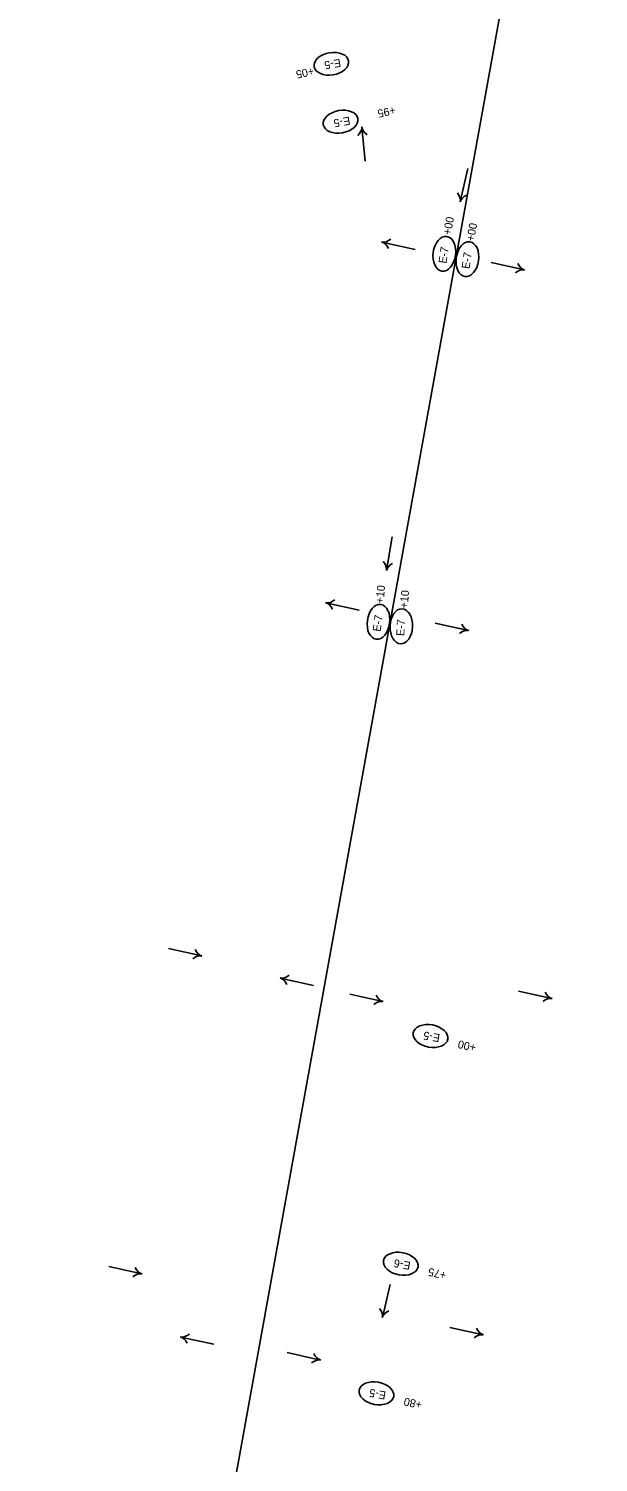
# Model space of a CAD drawing. Extents: x 669236 to 673912, y 735758 to 754788.
# Drawn here: x 670518 to 670963, y 741936 to 743056 of the extents above; entities that cross this region are included whole.
import ezdxf

# ---------------------------------------------------------------- set-up
doc = ezdxf.new("R2010")
doc.units = 0
for name, color, linetype in [('Default', 7, 'Continuous'), ('R_Erosion_2', 7, 'Continuous'), ('R_Erosion_3', 7, 'Continuous'), ('R_Flow Arrows', 7, 'Continuous')]:
    doc.layers.add(name, color=color, linetype=linetype)

msp = doc.modelspace()

# ---------------------------------------------------------------- linework, layer by layer
at = {"layer": 'Default'}
msp.add_line((670518, 741030.5), (670962.6, 743492), dxfattribs=at)
at = {"layer": 'R_Erosion_2'}
for centre, major_axis in [((670754.2, 743028.2), (-13.5, -2.2)), ((670761.4, 742983), (-13.5, -2.4)), ((670842.4, 742879.9), (1.9, 13.6)), ((670860.4, 742875.7), (1.9, 13.6)), ((670791, 742592.5), (1.8, 13.6)), ((670808.8, 742589), (0.6, 13.7))]:
    msp.add_ellipse(centre, major_axis=major_axis, ratio=0.638788, dxfattribs=at)
at = {"layer": 'R_Erosion_3'}
for centre in [(670831.6, 742269.1), (670808.4, 742091.3), (670789.4, 741990.1)]:
    msp.add_ellipse(centre, major_axis=(-13.5, 2.5), ratio=0.638788, dxfattribs=at)
at = {"layer": 'R_Flow Arrows'}
for p, q in [((670778, 742978.7), (670780.5, 742952.3)), ((670854.8, 742920.5), (670860.6, 742946.4)), ((670793.6, 742889), (670819.5, 742883.3)), ((670904.9, 742867.3), (670879, 742873.1)), ((670797.2, 742632.7), (670801.6, 742658.9)), ((670749.9, 742607.4), (670775.9, 742601.7)), ((670861.3, 742585.7), (670835.3, 742591.5)), ((670653, 742331.6), (670627.1, 742337.4)), ((670714.3, 742314.3), (670740.2, 742308.6)), ((670794.4, 742296), (670768.5, 742301.8)), ((670926.4, 742298.4), (670900.4, 742304.2)), ((670606.3, 742083.4), (670580.4, 742089.2)), ((670794, 742049.3), (670800.2, 742075.2)), ((670872.7, 742035.9), (670846.8, 742041.6)), ((670636.5, 742034.1), (670662.4, 742028.4)), ((670745.7, 742016.1), (670719.8, 742021.9))]:
    msp.add_line(p, q, dxfattribs=at)
for centre, major_axis, start_param, end_param in [((670757.9, 742977.3), (20.1, 1.9), 5.662936, 6.259934), ((670798, 742980.9), (-20.1, -1.9), 0.023252, 0.620249), ((670835.1, 742924.6), (19.7, -4.4), 0.023252, 0.620249), ((670874.4, 742915.7), (-19.7, 4.4), 5.662936, 6.259934), ((670788.8, 742869.5), (4.4, 19.7), 5.662936, 6.259934), ((670797.7, 742908.8), (-4.4, -19.7), 0.023252, 0.620249), ((670900.8, 742847.6), (4.4, 19.7), 0.023252, 0.620249), ((670909.7, 742886.9), (-4.4, -19.7), 5.662936, 6.259934), ((670777.3, 742635.8), (19.9, -3.3), 0.023252, 0.620249), ((670817, 742628.9), (-19.9, 3.3), 5.662936, 6.259934), ((670754.1, 742627.2), (-4.4, -19.7), 0.023252, 0.620249), ((670745.1, 742587.9), (4.4, 19.7), 5.662936, 6.259934), ((670866.1, 742605.3), (-4.4, -19.7), 5.662936, 6.259934), ((670857.1, 742566), (4.4, 19.7), 0.023252, 0.620249), ((670648.9, 742311.9), (4.4, 19.7), 0.023252, 0.620249), ((670657.8, 742351.2), (-4.4, -19.7), 5.662936, 6.259934), ((670709.5, 742294.8), (4.4, 19.7), 5.662936, 6.259934), ((670718.4, 742334.1), (-4.4, -19.7), 0.023252, 0.620249), ((670790.3, 742276.3), (4.4, 19.7), 0.023252, 0.620249), ((670799.2, 742315.6), (-4.4, -19.7), 5.662936, 6.259934), ((670922.3, 742278.7), (4.4, 19.7), 0.023252, 0.620249), ((670931.2, 742318), (-4.4, -19.7), 5.662936, 6.259934), ((670602.2, 742063.7), (4.4, 19.7), 0.023252, 0.620249), ((670611.1, 742103), (-4.4, -19.7), 5.662936, 6.259934), ((670774.3, 742053.8), (19.6, -4.8), 0.023252, 0.620249), ((670813.5, 742044.2), (-19.6, 4.8), 5.662936, 6.259934), ((670877.5, 742055.5), (-4.4, -19.7), 5.662936, 6.259934), ((670631.7, 742014.6), (4.4, 19.7), 5.662936, 6.259934), ((670640.6, 742053.9), (-4.4, -19.7), 0.023252, 0.620249), ((670868.6, 742016.1), (4.4, 19.7), 0.023252, 0.620249), ((670741.6, 741996.4), (4.4, 19.7), 0.023252, 0.620249), ((670750.6, 742035.7), (-4.4, -19.7), 5.662936, 6.259934)]:
    msp.add_ellipse(centre, major_axis=major_axis, ratio=0.5625, start_param=start_param, end_param=end_param, dxfattribs=at)

# ---------------------------------------------------------------- texts
at = {"layer": 'R_Erosion_2'}
for s, rotation, p in [('+05', 192.1215, (670739.9, 743025.7)), ('E-5', 189.2797, (670761.1, 743032.1)), ('+95', 192.4629, (670803.6, 742995.2)), ('E-5', 190.1319, (670768.3, 742987)), ('+00', 79.2728, (670847.4, 742894.2)), ('+00', 79.2728, (670865.5, 742889.3)), ('E-7', 81.9991, (670844, 742872)), ('E-7', 81.9991, (670862, 742867.8)), ('+10', 84.6001, (670794.9, 742606.7)), ('+10', 84.6001, (670813.7, 742602.8)), ('E-7', 82.5982, (670792.6, 742584.6)), ('E-7', 87.3558, (670811.1, 742581.3))]:
    msp.add_text(s, height=6.25, rotation=rotation, dxfattribs=at).set_placement(p)
at = {"layer": 'R_Erosion_3'}
for s, rotation, p in [('E-5', 169.6427, (670839.4, 742270.4)), ('+00', 167.5318, (670867.6, 742262.9)), ('E-6', 169.6427, (670816.4, 742092.6)), ('+75', 167.5318, (670844.4, 742085.1)), ('E-5', 169.6427, (670797.2, 741991.4)), ('+80', 167.5318, (670825.4, 741983.9))]:
    msp.add_text(s, height=6.25, rotation=rotation, dxfattribs=at).set_placement(p)

doc.saveas('drawing.dxf')
